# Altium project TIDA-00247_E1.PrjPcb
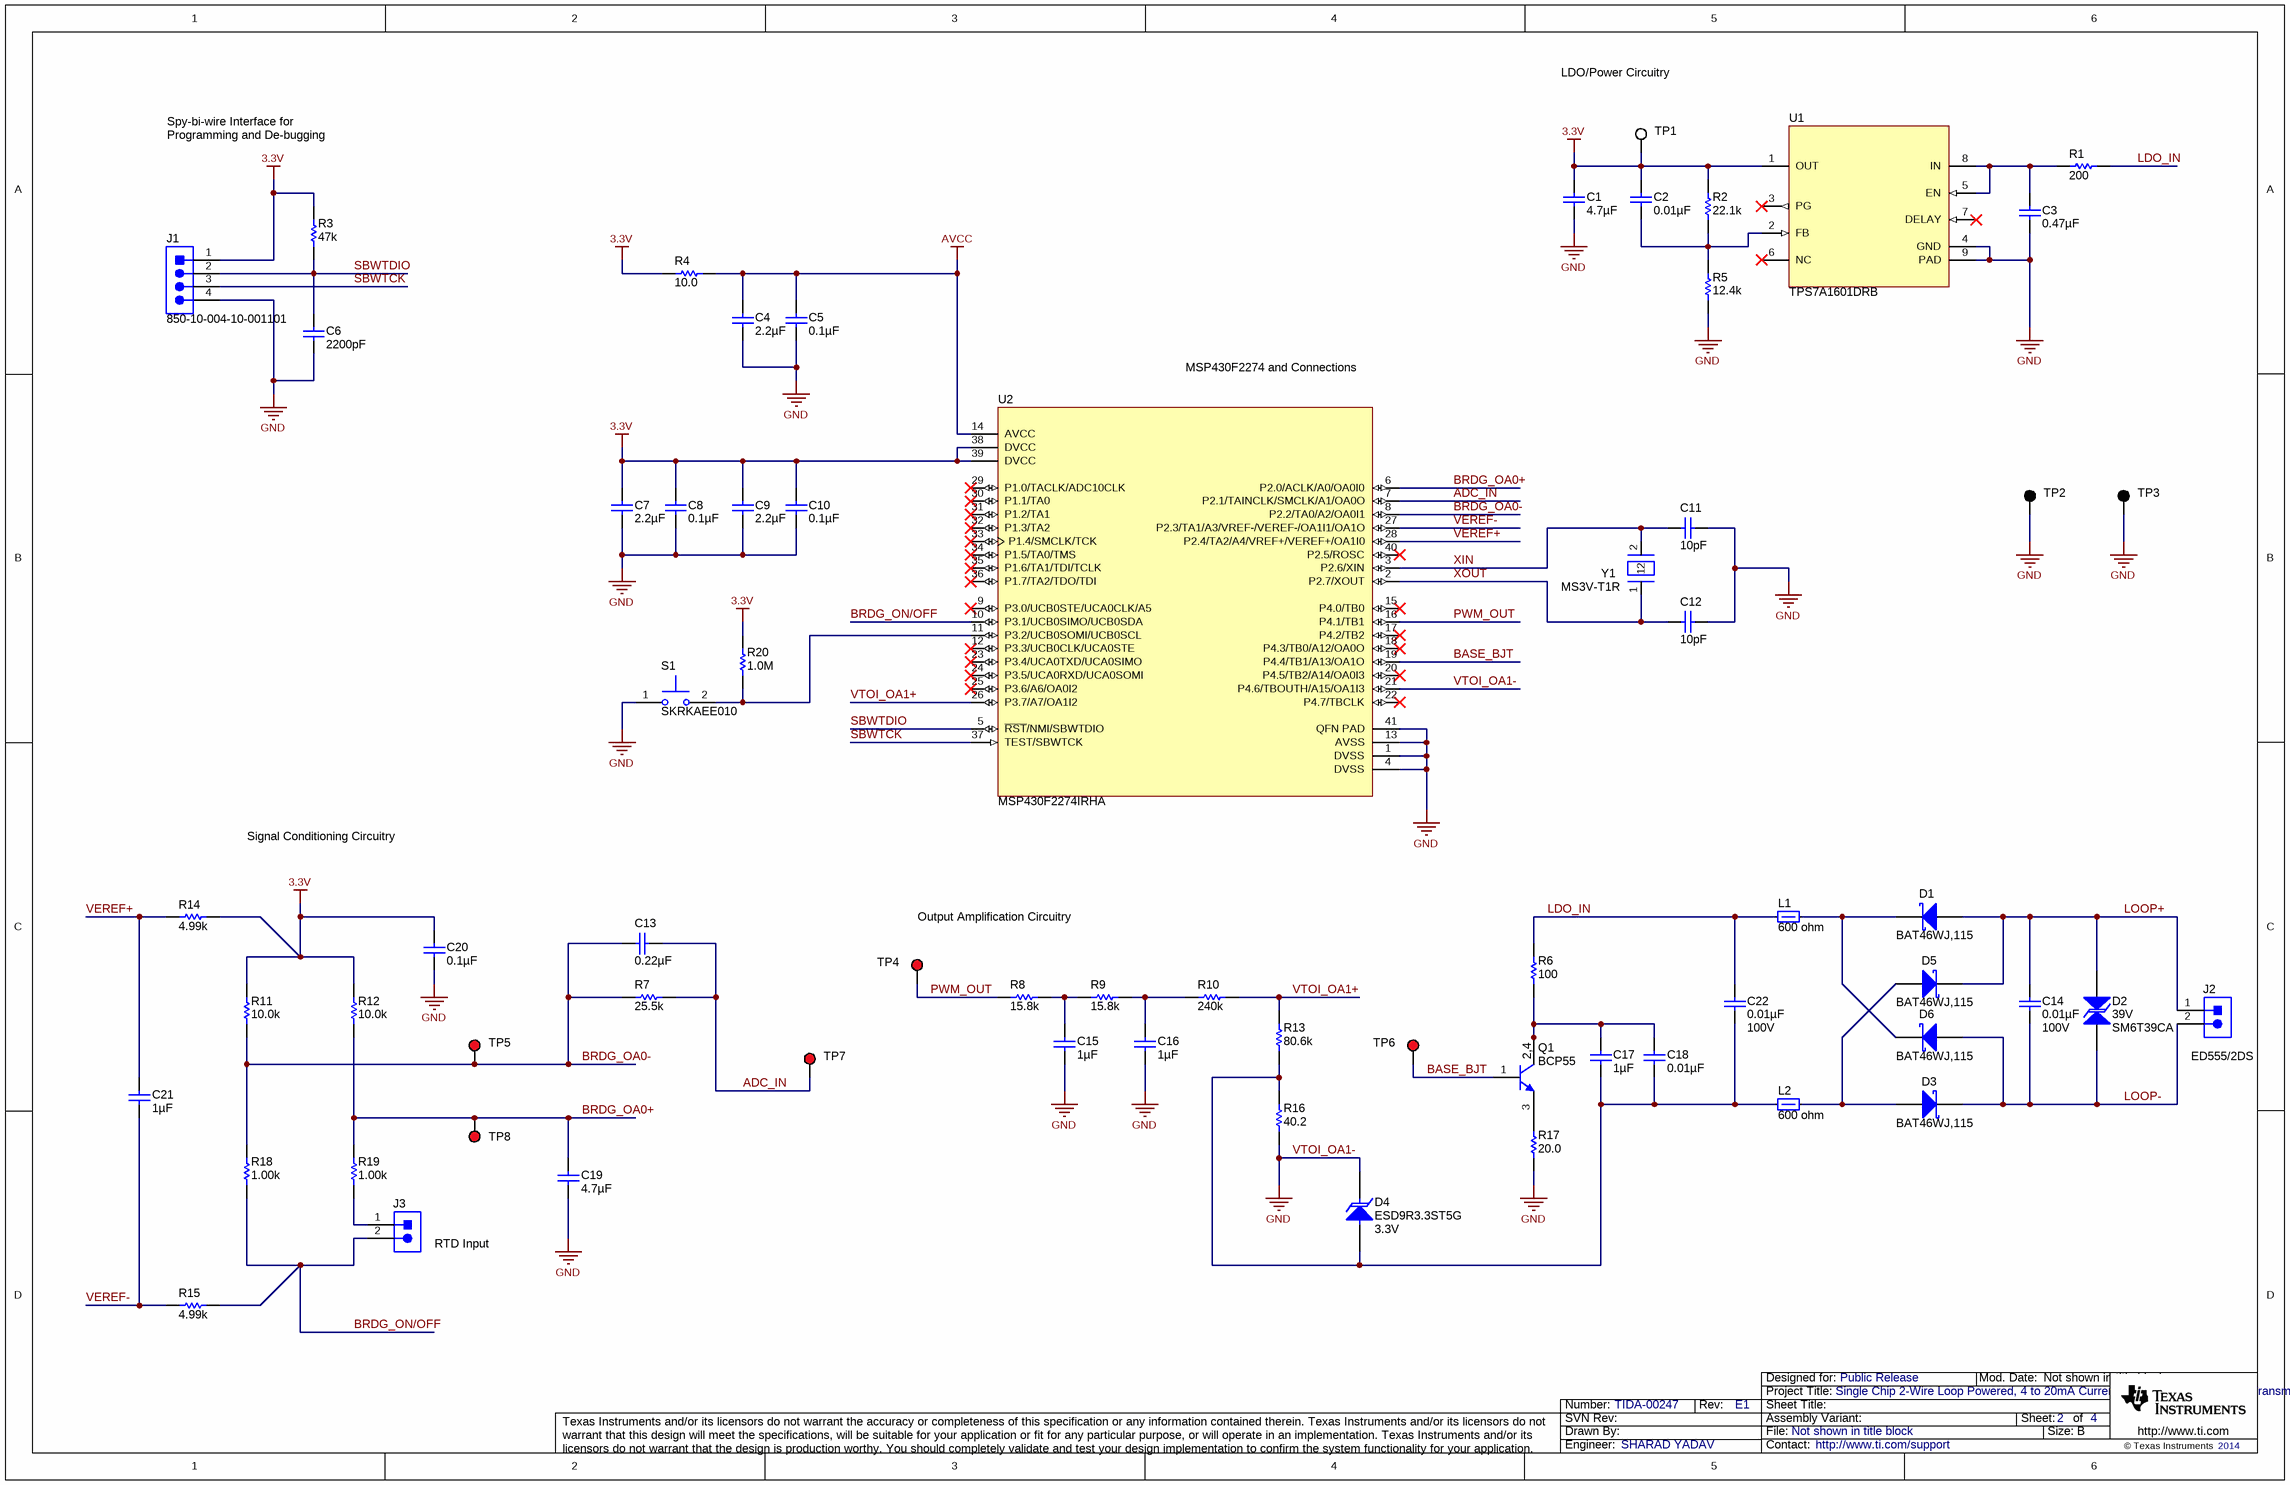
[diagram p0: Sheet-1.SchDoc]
TechSupport: http://www.ti.com/support; SCH_Rev: E1; PRJ_Title: Single Chip 2-Wire Loop Powered, 4 to 20mA Current Loop RTD Temperature Transmitter; PRJ_Number: TIDA-00247; PRJ_Engineer: SHARAD YADAV; PRJ_Customer: Public Release; PCB_Rev: E1; PCB_Layout: SHARAD YADAV; CopyrightYear: 2014
3 sheets, 72 parts. Net scope: global (net labels, ports and power ports of the same name join across sheets).
Board file: TIDA-00247_E1.PcbDoc
Sheets:
  Cover Sheet_ANSI-B.SchDoc
  Sheet-1.SchDoc
  Hardware_ANSI-B.SchDoc

## Sheet Cover Sheet_ANSI-B.SchDoc
size 431 x 279 mm; Date: Not shown in title block; ApprovedBy: Not shown in title block; CheckedBy: Not shown in title block; Author: Not shown in title block; CompanyName: Not shown in title block; Engineer: Not shown in title block; Organization: Not shown in title block; Address1: Not shown in title block; Address2: Not shown in title block; Address3: Not shown in title block; Address4: Not shown in title block; DocumentNumber: 1; Revision: Use project parameter SCH_Rev; SheetNumber: 1; SheetTotal: 4; PageSetup: Record=PageOptions|CenterHorizontal=True|CenterVertical=True|PrintScale=1.00|XCorrection=1.00|YCorrection=1.00|PrintKind=0|BorderSize=5000000|LeftOffset=0|BottomOffset=0|Orientation=2|PaperLength=1000|PaperWidth=1000|Scale=100|PaperSource=15|PrintQuality=600|MediaType=1|DitherType=10|PaperKind=Letter|PrintScaleMode=1

## Sheet Sheet-1.SchDoc
size 431 x 279 mm; Date: Not shown in title block; ApprovedBy: Not shown in title block; CheckedBy: Not shown in title block; Author: Not shown in title block; CompanyName: Not shown in title block; Engineer: Not shown in title block; Organization: Not shown in title block; Address1: Not shown in title block; Address2: Not shown in title block; Address3: Not shown in title block; Address4: Not shown in title block; DocumentNumber: 1; Revision: Use project parameter SCH_Rev; SheetNumber: 2; SheetTotal: 4; PageSetup: Record=PageOptions|CenterHorizontal=True|CenterVertical=True|PrintScale=1.00|XCorrection=1.00|YCorrection=1.00|PrintKind=0|BorderSize=5000000|LeftOffset=0|BottomOffset=0|Orientation=2|PaperLength=1000|PaperWidth=1000|Scale=100|PaperSource=15|PrintQuality=600|MediaType=1|DitherType=10|PaperKind=Letter|PrintScaleMode=1

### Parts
C1  ValueDisplayed: 4.7µF  [0805]  (hidden comment: GRM21BR71A475KA73L)
C2  ValueDisplayed: 0.01µF  [0402]  (hidden comment: GRM155R70J103KA01D)
C3  ValueDisplayed: 0.47µF  [1210]  (hidden comment: GRM32MR72A474KA01L)
C4  ValueDisplayed: 2.2µF  [0603]  (hidden comment: GRM188R71A225KE15D)
C5  ValueDisplayed: 0.1µF  [0402]  (hidden comment: GRM155R70J104KA01D)
C6  ValueDisplayed: 2200pF  [0402]  (hidden comment: GRM155R70J222KA01D)
C7  ValueDisplayed: 2.2µF  [0603]  (hidden comment: GRM188R71A225KE15D)
C8  ValueDisplayed: 0.1µF  [0402]  (hidden comment: GRM155R70J104KA01D)
C9  ValueDisplayed: 2.2µF  [0603]  (hidden comment: GRM188R71A225KE15D)
C10  ValueDisplayed: 0.1µF  [0402]  (hidden comment: GRM155R70J104KA01D)
C11  ValueDisplayed: 10pF  [0402]  (hidden comment: GRM1555C1H100JA01D)
C12  ValueDisplayed: 10pF  [0402]  (hidden comment: GRM1555C1H100JA01D)
C13  ValueDisplayed: 0.22µF  [0603]  (hidden comment: GRM188R70J224KA88D)
C14  ValueDisplayed: 0.01µF  Value2: 100V  [0603]  (hidden comment: CAP, CERM, 0.01uF, 100V, +/-10%, X7R, 0603)
C15  ValueDisplayed: 1µF  [0603]  (hidden comment: GRM188R70J105KA01D)
C16  ValueDisplayed: 1µF  [0603]  (hidden comment: GRM188R70J105KA01D)
C17  ValueDisplayed: 1µF  [0805_HV]  (hidden comment: 08055C105KAT2A)
C18  ValueDisplayed: 0.01µF  [0805_HV]  (hidden comment: 08055C103JAT2A)
C19  ValueDisplayed: 4.7µF  [0603]  (hidden comment: C0603C475K9PACTU)
C20  ValueDisplayed: 0.1µF  [0402]  (hidden comment: GRM155R70J104KA01D)
C21  ValueDisplayed: 1µF  [0603]  (hidden comment: GRM188R70J105KA01D)
C22  ValueDisplayed: 0.01µF  Value2: 100V  [0603]  (hidden comment: CAP, CERM, 0.01uF, 100V, +/-10%, X7R, 0603)
D1  BAT46WJ,115  [SOD-323F]
D2  value 39V  [SMB]  (hidden comment: SM6T39CA)
D3  BAT46WJ,115  [SOD-323F]
D4  ESD9R3.3ST5G  value 3.3V  [SOD-923]
D5  BAT46WJ,115  [SOD-323F]
D6  BAT46WJ,115  [SOD-323F]
J1  850-10-004-10-001101  [Preci-dip_850-xx-004-10-001101]
J2  ED555/2DS  [TERM_BLK_ED555-2DS]
J3  RTD Input  [TERM_BLK_ED555-2DS]
L1  value 600 ohm  [0603]  (hidden comment: BLM18KG601SN1D)
L2  value 600 ohm  [0603]  (hidden comment: BLM18KG601SN1D)
Q1  BCP55  [SOT-223]
R1  value 200  [0805]  (hidden comment: CRCW0805200RFKEA)
R2  ValueDisplayed: 22.1k  [0603]  (hidden comment: RG1608P-2212-B-T5)
R3  value 47k  [0402]  (hidden comment: CRCW040247K0JNED)
R4  value 10.0  [0603]  (hidden comment: CRCW060310R0FKEA)
R5  ValueDisplayed: 12.4k  [0603]  (hidden comment: RG1608P-1242-B-T5)
R6  value 100  [0805]  (hidden comment: CRCW0805100RFKEA)
R7  ValueDisplayed: 25.5k  [0603]  (hidden comment: RT0603BRD0725K5L)
R8  ValueDisplayed: 15.8k  [0603]  (hidden comment: RT0603BRD0715K8L)
R9  ValueDisplayed: 15.8k  [0603]  (hidden comment: RT0603BRD0715K8L)
R10  ValueDisplayed: 240k  [0603]  (hidden comment: RT0603BRD07240KL)
R11  ValueDisplayed: 10.0k  [0603]  (hidden comment: RT0603BRD0710KL)
R12  ValueDisplayed: 10.0k  [0603]  (hidden comment: RT0603BRD0710KL)
R13  value 80.6k  [0805]  (hidden comment: RT0805BRD0780K6L)
R14  ValueDisplayed: 4.99k  [0402]  (hidden comment: CRCW04024K99FKED)
R15  ValueDisplayed: 4.99k  [0402]  (hidden comment: CRCW04024K99FKED)
R16  ValueDisplayed: 40.2  [0805]  (hidden comment: RT0805BRD0740R2L)
R17  value 20.0  [0805]  (hidden comment: CRCW080520R0FKEA)
R18  ValueDisplayed: 1.00k  [0603]  (hidden comment: RT0603BRD071KL)
R19  ValueDisplayed: 1.00k  [0603]  (hidden comment: RT0603BRD071KL)
R20  ValueDisplayed: 1.0M  [0402]  (hidden comment: CRCW04021M00JNED)
S1  SKRKAEE010  [SW_SKRKAEE010]
TP1  5002  [Keystone5002]  (value not drawn)
TP2  5001  [Keystone5001]  (value not drawn)
TP3  5001  [Keystone5001]  (value not drawn)
TP4  5000  [Keystone5000]  (value not drawn)
TP5  5000  [Keystone5000]  (value not drawn)
TP6  5000  [Keystone5000]  (value not drawn)
TP7  5000  [Keystone5000]  (value not drawn)
TP8  5000  [Keystone5000]  (value not drawn)
U1  TPS7A1601DRB  [DRB0008B]
U2  MSP430F2274IRHA  [RHA0040B]
Y1  MS3V-T1R  [CRYSTAL-MS3V-T1R]

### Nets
3.3V: C1.1 C2.1 C7.1 C8.1 C9.1 C10.1 C20.2 J1.1 R2.2 R3.2 R4.2 R11.2 R12.2 R14.2 R20.2 TP1.1 U1.1(OUT) U2.38(DVCC) U2.39(DVCC)
AVCC: C4.1 C5.1 R4.1 U2.14(AVCC)
VTOI_OA1-: C1.2 C3.2 C4.2 C5.2 C6.2 C7.2 C8.2 C9.2 C10.2 C11.2 C12.2 C15.2 C16.2 C19.2 C20.1 D4.1(K) J1.4 R5.1 R16.1 R17.1 S1.1 TP2.1 TP3.1 U1.4(GND) U1.9(PAD) U2.1(DVSS) U2.4(DVSS) U2.13(AVSS) U2.21(P4.6/TBOUTH/A15/OA1I3) U2.41(QFN_PAD)  [also labelled GND]
ADC_IN: C13.1 R7.2 TP7.1 U2.7(P2.1/TAINCLK/SMCLK/A1/OA0O)
BASE_BJT: Q1.1(B) TP6.1 U2.19(P4.4/TB1/A13/OA1O)
BRDG_OA0+: C19.1 R12.1 R19.2 TP8.1 U2.6(P2.0/ACLK/A0/OA0I0)
BRDG_OA0-: C13.2 R7.1 R11.1 R18.2 TP5.1 U2.8(P2.2/TA0/A2/OA0I1)
BRDG_ON/OFF: J3.2 R15.2 R18.1 U2.10(P3.1/UCB0SIMO/UCB0SDA)
LDO_IN: C22.1 L1.1 R1.2 R6.2
LOOP+: C14.1 D1.2(A) D2.1 D5.1(K) J2.1
LOOP-: C14.2 D2.2 D3.1(K) D6.2(A) J2.2
PWM_OUT: R8.1 TP4.1 U2.16(P4.1/TB1)
SBWTCK: J1.3 U2.37(TEST/SBWTCK)
SBWTDIO: C6.1 J1.2 R3.1 U2.5(~{RST}/NMI/SBWTDIO)
VEREF+: C21.1 R14.1 U2.28(P2.4/TA2/A4/VREF+/VEREF+/OA1I0)
VEREF-: C21.2 R15.1 U2.27(P2.3/TA1/A3/VREF-/VEREF-/OA1I1/OA1O)
VTOI_OA1+: R10.2 R13.2 U2.26(P3.7/A7/OA1I2)
XIN: C11.1 U2.3(P2.6/XIN) Y1.2
XOUT: C12.1 U2.2(P2.7/XOUT) Y1.1
NetC2_2: C2.2 R2.1 R5.2 U1.2(FB)
NetC3_1: C3.1 R1.1 U1.5(EN) U1.8(IN)
NetC15_1: C15.1 R8.2 R9.1
NetC16_1: C16.1 R9.2 R10.1
NetC17_1: C17.1 C18.1 Q1.2(C) Q1.4(C) R6.1
NetC17_2: C17.2 C18.2 C22.2 D4.2(A) L2.1 R13.1 R16.2
NetD1_1: D1.1(K) D6.1(K) L1.2
NetD3_2: D3.2(A) D5.2(A) L2.2
NetJ3_1: J3.1 R19.1
NetQ1_3: Q1.3(E) R17.2
NetR20_1: R20.1 S1.2 U2.11(P3.2/UCB0SOMI/UCB0SCL)

Not connected (* = marked no-connect by the designer): U1 3(PG)* 6(NC)* 7(DELAY)*; U2 9(P3.0/UCB0STE/UCA0CLK/A5)* 12(P3.3/UCB0CLK/UCA0STE)* 15(P4.0/TB0)* 17(P4.2/TB2)* 18(P4.3/TB0/A12/OA0O)* 20(P4.5/TB2/A14/OA0I3)* 22(P4.7/TBCLK)* 23(P3.4/UCA0TXD/UCA0SIMO)* 24(P3.5/UCA0RXD/UCA0SOMI)* 25(P3.6/A6/OA0I2)* 29(P1.0/TACLK/ADC10CLK)* 30(P1.1/TA0)* 31(P1.2/TA1)* 32(P1.3/TA2)* 33(P1.4/SMCLK/TCK)* 34(P1.5/TA0/TMS)* 35(P1.6/TA1/TDI/TCLK)* 36(P1.7/TA2/TDO/TDI)* 40(P2.5/ROSC)*

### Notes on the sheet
- LDO/Power Circuitry
- Spy-bi-wire Interface for Programming and De-bugging
- MSP430F2274 and Connections
- Signal Conditioning Circuitry
- Output Amplification Circuitry

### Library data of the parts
C1 = GRM21BR71A475KA73L: CAP, CERM, 4.7 µF, 10 V, +/- 10%, X7R, 0805; Manufacturer: MuRata; Polarized: N; CompType: Capacitor; Value: 4.7uF; U/M: EA; Cap_F: 0.0000047; Tolerance_%: 10; Value1: Unknown; Value2: 10V; TaMin_C: -55; TaMax_C: 125
C2 = GRM155R70J103KA01D: CAP, CERM, 0.01 µF, 6.3 V, +/- 10%, X7R, 0402; Manufacturer: MuRata; Polarized: N; CompType: Capacitor; Value: 0.01uF; U/M: EA; Cap_F: 0.00000001; Tolerance_%: 10; Value1: Unknown; VDC_V: 6.3; Value2: 6.3V; TaMin_C: -55; TaMax_C: 125
C3 = GRM32MR72A474KA01L: CAP, CERM, 0.47 µF, 100 V, +/- 10%, X7R, 1210; Manufacturer: MuRata; Polarized: N; CompType: Capacitor; Value: 0.47uF; U/M: EA; Cap_F: 0.00000047; Tolerance_%: 10; Value1: Unknown; VDC_V: 100; Value2: 100V; TaMin_C: -55; TaMax_C: 125
C4 C7 C9 = GRM188R71A225KE15D: CAP, CERM, 2.2 µF, 10 V, +/- 10%, X7R, 0603; Manufacturer: MuRata; Polarized: N; CompType: Capacitor; Value: 2.2uF; U/M: EA; Cap_F: 0.0000022; Tolerance_%: 10; ESR_ohm: 0.009; Value1: 0.009 ohm; Value2: 10V; TaMin_C: -55; TaMax_C: 125
C5 C8 C10 C20 = GRM155R70J104KA01D: CAP, CERM, 0.1 µF, 6.3 V, +/- 10%, X7R, 0402; Manufacturer: MuRata; Polarized: N; CompType: Capacitor; Value: 0.1uF; U/M: EA; Cap_F: 0.0000001; Tolerance_%: 10; Value1: Unknown; VDC_V: 6.3; Value2: 6.3V; TaMin_C: -55; TaMax_C: 125
C6 = GRM155R70J222KA01D: CAP, CERM, 2200pF, 6.3V, +/-10%, X7R, 0402; Manufacturer: MuRata; Polarized: N; CompType: Capacitor; U/M: EA; Cap_F: 0.0000000022; Tolerance_%: 10; Value1: Unknown; VDC_V: 6.3; TaMin_C: -55; TaMax_C: 125
C11 C12 = GRM1555C1H100JA01D: CAP, CERM, 10pF, 50V, +/-5%, C0G/NP0, 0402; Manufacturer: MuRata; Polarized: N; CompType: Capacitor; U/M: EA; Cap_F: 0.00000000001; Tolerance_%: 5; Value1: Unknown; VDC_V: 50; TaMin_C: -55; TaMax_C: 125
C13 = GRM188R70J224KA88D: CAP, CERM, 0.22 µF, 6.3 V, +/- 10%, X7R, 0603; Manufacturer: MuRata; Polarized: N; CompType: Capacitor; Value: 0.22uF; U/M: EA; Cap_F: 0.00000022; Tolerance_%: 10; Value1: Unknown; VDC_V: 6.3; Value2: 6.3V; TaMin_C: -55; TaMax_C: 125
C14 C22 = GRM188R72A103KA01D: Manufacturer: MuRata; Polarized: N; CompType: Capacitor; U/M: EA; Cap_F: 0.00000001; Tolerance_%: 10; Value1: Unknown; VDC_V: 100; TaMin_C: -55; TaMax_C: 125
C15 C16 C21 = GRM188R70J105KA01D: CAP, CERM, 1 µF, 6.3 V, +/- 10%, X7R, 0603; Manufacturer: MuRata; Polarized: N; CompType: Capacitor; Value: 1uF; U/M: EA; Cap_F: 0.000001; Tolerance_%: 10; Value1: Unknown; VDC_V: 6.3; Value2: 6.3V; TaMin_C: -55; TaMax_C: 125
C17 = 08055C105KAT2A: CAP, CERM, 1uF, 50V, +/-10%, X7R, 0805; Manufacturer: AVX; Polarized: N; CompType: Capacitor; U/M: EA; Cap_F: 0.000001; Tolerance_%: 10; Value1: Unknown; VDC_V: 50; TaMin_C: -55; TaMax_C: 125; Cap_Case: 0805
C18 = 08055C103JAT2A: CAP, CERM, 0.01uF, 50V, +/-5%, X7R, 0805; Manufacturer: AVX; Polarized: N; CompType: Capacitor; U/M: EA; Cap_F: 0.00000001; Tolerance_%: 5; ESR_Ohm: 0.078; Value1: 0.078 ohm; VDC_V: 50; TaMin_C: -55; TaMax_C: 125; Cap_Case: 0805
C19 = C0603C475K9PACTU: CAP, CERM, 4.7 µF, 6.3 V, +/- 10%, X5R, 0603; Manufacturer: Kemet; Polarized: N; CompType: Capacitor; Value: 4.7uF; U/M: EA; Cap_F: 0.0000047; Tolerance_%: 10; ESR_ohm: 0.006; Value1: 0.006 ohm; VDC_V: 6.3; Value2: 6.3V; IRMS_A: 7.24; TaMin_C: -55; TaMax_C: 85
D1 D3 D5 D6 = BAT46WJ,115: Diode, Schottky, 100V, 0.25A, SOD-323F; Manufacturer: NXP Semiconductor; U/M: EA; Vf_V: 0.85; Value2: 0.85V; Io_A: 0.25; Vr_V: 100; TJmax_C: 150
D2 = SMBJ40CA-13-F: TVS DIODE 33.3VWM 69.7VC SMB; Manufacturer: STMicroelectronics; U/M: EA; Power_W: 600; Value1: 600W
D4 = ESD9R3.3ST5G: Diode, TVS, Uni, 3.3V, 0.15W, SOD-923; Manufacturer: ON Semiconductor; U/M: EA; Power_W: 0.15; Vr_V: 3.3
J1 = 850-10-004-10-001101: Header, 50mil, 4x1, Gold, TH; Manufacturer: Preci-Dip; SymbolCreator: a0412235; U/M: EA
J2 J3 = ED555/2DS: Terminal Block, 6A, 3.5mm Pitch, 2-Pos, TH; Manufacturer: On-Shore Technology; SymbolCreator: a0412235; CompType: Connector; U/M: EA
L1 L2 = BLM18KG601SN1D: Ferrite Bead, 600 ohm @ 100MHz, 1.3A, 0603; Manufacturer: MuRata; Imax_A: 1.3; DCR_ohm: 0.15; Value1: 0.15 ohm; ZTyp@100MHz_Ohm: 600
Q1 = BCP55, Fairchild Semiconductor: Transistor, NPN, 60 V, 1.5 A, SOT-223; CompType: BJT; PNP: 0; NPN: 1; Vceo_V: 60; Vcesat1_V: 0.5; Value: 60 V; IcRated_A: 1.5; Value1: 1.5 A; HfeMax: 250; TaMin_C: -55; TaMax_C: 150; U/M: EA
R1 = CRCW0805200RFKEA: RES, 200 ohm, 1%, 0.125W, 0805; Manufacturer: Vishay-Dale; CompType: Resistor; Value_Code: 200R; Tolerance_%: 1; Power_W: 0.125; VDC_V: 150; TempCo: 100 ppm/C; EIA_Code: E96; U/M: EA
R2 = RG1608P-2212-B-T5: RES, 22.1 k, 0.1%, 0.1 W, 0603; Manufacturer: Susumu Co Ltd; CompType: Resistor; Value: 22.1k; Res_ohm: 22100; Value_Code: 22k1; Tolerance_%: 0.1; Value2: 0.1W; VDC_V: 75; TempCo: 25 ppm/C; EIA_Code: E192; U/M: EA
R3 = CRCW040247K0JNED: RES, 47k ohm, 5%, 0.063W, 0402; Manufacturer: Vishay-Dale; CompType: Resistor; Res_ohm: 47000; Value_Code: 47k0; Tolerance_%: 5; Power_W: 0.063; VDC_V: 50; TempCo: 200 ppm/C; EIA_Code: E24; U/M: EA
R4 = CRCW060310R0FKEA: RES, 10.0 ohm, 1%, 0.1W, 0603; Manufacturer: Vishay-Dale; CompType: Resistor; Res_ohm: 10; Value_Code: 10R0; Tolerance_%: 1; Power_W: 0.1; VDC_V: 75; TempCo: 100 ppm/C; EIA_Code: E96; U/M: EA
R5 = RG1608P-1242-B-T5: RES, 12.4 k, 0.1%, 0.1 W, 0603; Manufacturer: Susumu Co Ltd; CompType: Resistor; Value: 12.4k; Res_ohm: 12400; Value_Code: 12k4; Tolerance_%: 0.1; Value2: 0.1W; VDC_V: 75; TempCo: 25 ppm/C; EIA_Code: E192; U/M: EA
R6 = CRCW0805100RFKEA: RES, 100 ohm, 1%, 0.125W, 0805; Manufacturer: Vishay-Dale; CompType: Resistor; Value_Code: 100R; Tolerance_%: 1; Power_W: 0.125; VDC_V: 150; TempCo: 100 ppm/C; EIA_Code: E96; U/M: EA
R7 = RT0603BRD0725K5L: RES, 25.5 k, 0.1%, 0.1 W, 0603; Manufacturer: Yageo America; CompType: Resistor; Res_ohm: 25500; Value: 25.5k; Value_Code: 25k5; Tolerance_%: 0.1; Value2: 0.1W; VDC_V: 75; TempCo: 25 ppm/C; EIA_Code: E192; U/M: EA
R8 R9 = RT0603BRD0715K8L: RES, 15.8 k, 0.1%, 0.1 W, 0603; Manufacturer: Yageo America; CompType: Resistor; Value: 15.8k; Res_ohm: 15800; Value_Code: 15k8; Tolerance_%: 0.1; Value2: 0.1W; VDC_V: 75; TempCo: 25 ppm/C; EIA_Code: E192; U/M: EA
R10 = RT0603BRD07240KL: RES, 240 k, 0.1%, 0.1 W, 0603; Manufacturer: Yageo America; CompType: Resistor; Value: 240k; Res_ohm: 240000; Tolerance_%: 0.1; Value2: 0.1W; VDC_V: 75; TempCo: 25 ppm/C; EIA_Code: E192; U/M: EA
R11 R12 = RT0603BRD0710KL: RES, 10.0 k, 0.1%, 0.1 W, 0603; Manufacturer: Yageo America; CompType: Resistor; Res_ohm: 10000; Value: 10.0k; Value_Code: 10k0; Tolerance_%: 0.1; Value2: 0.1W; VDC_V: 75; TempCo: 25 ppm/C; EIA_Code: E192; U/M: EA
R13 = RT0805BRD0780K6L: RES, 80.6k ohm, 0.1%, 0.125W, 0805; Manufacturer: Yageo America; CompType: Resistor; Res_ohm: 80600; Value_Code: 80k6; Tolerance_%: 0.1; Power_W: 0.125; VDC_V: 150; TempCo: 25 ppm/C; EIA_Code: E192; U/M: EA
R14 R15 = CRCW04024K99FKED: RES, 4.99 k, 1%, 0.063 W, 0402; Manufacturer: Vishay-Dale; CompType: Resistor; Res_ohm: 4990; Value: 4.99k; Value_Code: 4k99; Tolerance_%: 1; Power_W: 0.063; Value2: 0.063W; VDC_V: 50; TempCo: 100 ppm/C; EIA_Code: E96; U/M: EA
R16 = RT0805BRD0740R2L: RES, 40.2, 0.1%, 0.125 W, 0805; Manufacturer: Yageo America; CompType: Resistor; Value: 40.2; Value_Code: 40R2; Tolerance_%: 0.1; Power_W: 0.125; Value2: 0.125W; VDC_V: 150; TempCo: 25 ppm/C; EIA_Code: E192; U/M: EA
R17 = CRCW080520R0FKEA: RES, 20.0 ohm, 1%, 0.125W, 0805; Manufacturer: Vishay-Dale; CompType: Resistor; Res_ohm: 20; Value_Code: 20R0; Tolerance_%: 1; Power_W: 0.125; VDC_V: 150; TempCo: 100 ppm/C; EIA_Code: E96; U/M: EA
R18 R19 = RT0603BRD071KL: RES, 1.00 k, 0.1%, 0.1 W, 0603; Manufacturer: Yageo America; CompType: Resistor; Res_ohm: 1000; Value: 1.00k; Value_Code: 1k00; Tolerance_%: 0.1; Value2: 0.1W; VDC_V: 75; TempCo: 25 ppm/C; EIA_Code: E192; U/M: EA
R20 = CRCW04021M00JNED: RES, 1.0 M, 5%, 0.063 W, 0402; Manufacturer: Vishay-Dale; CompType: Resistor; Res_ohm: 1000000; Value: 1.0Meg; Value_Code: 1M00; Tolerance_%: 5; Power_W: 0.063; Value2: 0.063W; VDC_V: 50; TempCo: 200 ppm/C; EIA_Code: E24; U/M: EA
S1 = SKRKAEE010: Switch, Push Button, SMD; Manufacturer: Alps; SymbolCreator: a0412235; Circuit: SPST-NO; VDC_V: 12; SwitchFunction: Off-Mom; PositionCount: 1; CurrentRating_mA: 50
TP1 = 5002: Test Point, Miniature, White, TH; Manufacturer: Keystone; CompType: Test Point Loop; U/M: EA
TP2 TP3 = 5001: Test Point, Miniature, Black, TH; Manufacturer: Keystone; CompType: Test Point Loop; U/M: EA
TP4-TP8 = 5000: Test Point, Miniature, Red, TH; Manufacturer: Keystone; CompType: Test Point Loop; U/M: EA
U1 = TPS7A1601DRB: 60-V, 5-µA IQ, 100-mA, Low-Dropout Voltage Regulator with Enable and Power-Good, DRB0008B; Alternate Manufacturer: None; Manufacturer: Texas Instruments; SymbolCreator: a0411947; CompType: IC; U/M: EA
U2 = MSP430F2274IRHA: 16-bit Ultra-Low-Power Microcontroller, 32 KB Flash, 1 K RAM, RHA0040B; Alternate Manufacturer: None; Manufacturer: Texas Instruments; SymbolCreator: Altium; CompType: IC; U/M: EA
Y1 = CRYSTAL_MS3V-T1R: Crystal, Tuning Fork, 30kHz - 200kHz, SMD; Manufacturer: Micro Crystal AG; Area: 18.699; Value: {Value}

## Sheet Hardware_ANSI-B.SchDoc
size 431 x 279 mm; Date: Not shown in title block; ApprovedBy: Not shown in title block; CheckedBy: Not shown in title block; Author: Not shown in title block; CompanyName: Not shown in title block; Engineer: Not shown in title block; Organization: Not shown in title block; Address1: Not shown in title block; Address2: Not shown in title block; Address3: Not shown in title block; Address4: Not shown in title block; DocumentNumber: 1; Revision: Use project parameter SCH_Rev; SheetNumber: 4; SheetTotal: 4; PageSetup: Record=PageOptions|CenterHorizontal=True|CenterVertical=True|PrintScale=1.00|XCorrection=1.00|YCorrection=1.00|PrintKind=0|BorderSize=5000000|LeftOffset=0|BottomOffset=0|Orientation=2|PaperLength=1000|PaperWidth=1000|Scale=100|PaperSource=15|PrintQuality=600|MediaType=1|DitherType=10|PaperKind=Letter|PrintScaleMode=1
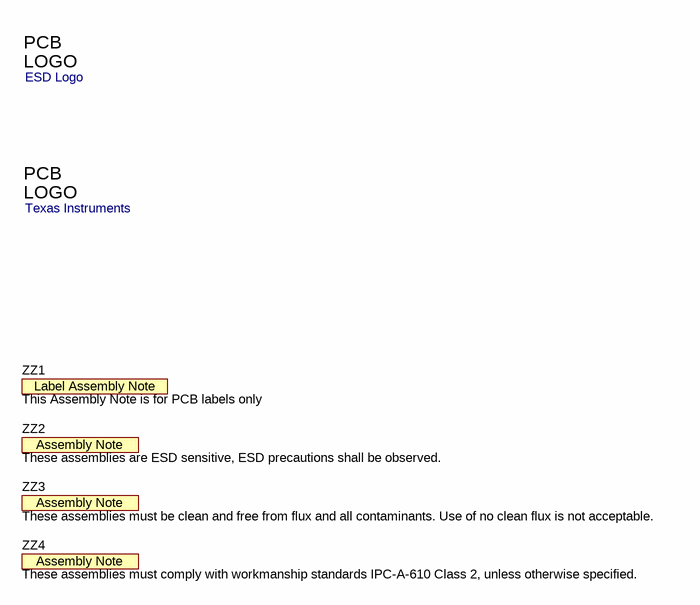
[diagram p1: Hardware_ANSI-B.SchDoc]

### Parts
Logo1  ESD Logo  [ESD_Overlay_Medium]  (no BOM)
Logo2  Texas Instruments  [TI_Stacked_Overlay_Small]  (no BOM)
ZZ1  This Assembly Note is for PCB labels only  [AssemblyNoteLabel]  (no BOM)
ZZ2  These assemblies are ESD sensitive, ESD precautions shall be observed.  [AssemblyNote]  (no BOM)
ZZ3  These assemblies must be clean and free from flux and all contaminants. Use of no clean flux is not acceptable.  [AssemblyNote]  (no BOM)
ZZ4  These assemblies must comply with workmanship standards IPC-A-610 Class 2, unless otherwise specified.  [AssemblyNote]  (no BOM)

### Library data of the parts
Logo1 Logo2 = TI_Logo: Texas Instrument Corporate Signature; SymbolCreator: a0412235
ZZ1 = AssemblyNoteLabel: SymbolCreator: a0412235
ZZ2-ZZ4 = AssemblyNote: SymbolCreator: codlsc

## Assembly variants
001: not fitted C17 C21 R14 R15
